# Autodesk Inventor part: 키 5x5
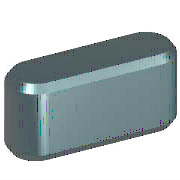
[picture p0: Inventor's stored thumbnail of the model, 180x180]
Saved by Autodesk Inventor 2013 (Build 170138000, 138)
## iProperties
IsCustomPart: 1
Created: 2012-02
Part Number: 키 5x5
Material: 강철, 연강
Description: 키 및 해당 키홈
Document SubType Name: Modeling
Standard: KS B 1311
Designer: mduedu
Standards Organization: KS
Language: ko-KR
Size Designation: 5 x 5 x 12
Categories: <MemberInstance><Categories><Category DisplayName="샤프트 부품" InternalName="7f7aeb1f-a693-4053-b835-cee3144e0d98" Mnemonic="SHFT"><Category DisplayName="키" Interna
Density: 1 g/cm^3
Author: mduedu
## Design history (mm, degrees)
workplane "Work Plane1"
workplane "Work Plane2"
sketch "스케치1"
  geometry: L1 (2.5, 2.5)-(9.5, 2.5); L2 (9.5, -2.5)-(2.5, -2.5); L3 (0, 9.4)-(0, -7.4) reference; L4 (-5, 0)-(30, 0) reference; L5 (12, 0)-(12, 7); A1 r 2.5 centre (2.5, 0) between (2.5, 2.5) and (2.5, -2.5); A2 r 2.5 centre (9.5, 0) between (9.5, -2.5) and (9.5, 2.5)
  constraints: 6 end point, 5 point on circle, 4 tangent, 3 point on line, 2 centre point, 1 horizontal, 1 parallel, 1 perpendicular
  dimensions: "d0" = 2.5 radius of A1 (= 0.5 x PB); "d13" = 2.5 radius of A2 (= 0.5 x PB); "d14" = 12 distance between parallel lines of L5 L3 (= NLG)
extrude "본체1" new body sketch "스케치1" taper "d3" = 0 deg; stored distance "d4" = 10
workplane "Work Plane3"
body "Solid1"
chamfer "모따기1" distance "d8" = 0.4 (= PHH); stored, may be unused: second distance "d9" = 0.4 (= PHH), angle "d15" = 45 deg
other parameters: "d1" = -3 (= -PNT), "d2" = 2 (= PH - PNT), "NLG" = 12 [user parameter; used in 3 equation terms], "PB" = 5 [user parameter; used in 2 equation terms], "PNT" = 3 [user parameter; used in 2 equation terms], "PH" = 5 [user parameter; used in 1 equation term], "PHH" = 0.4 [user parameter; used in 2 equation terms], "d10" = 0, "d16" = 0, "d17" = 0, "d18" = 0, "WDMIN" = 12 [user parameter], "PLB2" = 12 (= NLG) [user parameter], "WDMAX" = 17 [user parameter], "PLB1" = 12 (= NLG) [user parameter], "RR" = 0.16 [user parameter], "PUEB" = 2.3 [user parameter]
